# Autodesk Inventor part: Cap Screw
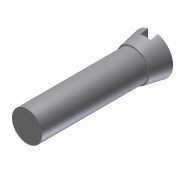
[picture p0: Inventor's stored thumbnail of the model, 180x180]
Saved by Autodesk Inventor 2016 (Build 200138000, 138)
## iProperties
Shininess: 77.0
Length Units: 11269
Angle Units: 11279
Time Units: 11290
Mass Units: 11283
Length Display Precision: 3
Angle Display Precision: 2
Created: 2002-02
Part Number: Cap Screw
Document SubType Name: Modeling
Designer: ***
Density: 1 g/cm^3
Material: Generic
Appearance: Default
Density: 0.0
Volumn: 0.0
Area: 0.0
PropertySet Name: Model Information
Control State: 0
Master: False
Checked Out: False
Author: ***
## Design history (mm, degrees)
sketch "Sketch1"
  geometry: L1 (0, 27.83)-(4, 27.83); L2 (4, 27.83)-(3.25, 23.83); L3 (3.25, 23.83)-(0, 23.83); L4 (0, 23.83)-(0, 27.83)
  constraints: 8 end point, 1 horizontal, 1 parallel, 1 perpendicular, 1 point on line
  dimensions: "d2" = 4 distance from line of L1 L2.end; "d5" = 8 diameter of L1.end L4; "d6" = 6.5 diameter of L3.start L4; "d14" = 4 distance of L3.end L1.start
revolve "Revolution1" sketch "Sketch1" stored, may be unused: angle "d7" = 90 deg
sketch "Sketch2"
  geometry: C1 r 3 at (0, 0)
  constraints: 1 centre point
  dimensions: "d8" = 6 diameter of C1
extrude "Extrusion1" join sketch "Sketch2" distance "d9" = 21; taper "d10" = 0 deg
sketch "Sketch3"
  geometry: L1 (-1, 28.967)-(1, 28.967); L2 (1, 28.967)-(1, 26.33); L3 (1, 26.33)-(-1, 26.33); L4 (-1, 26.33)-(-1, 28.967); L5 (-4, 27.83)-(4, 27.83) reference
  constraints: 8 end point, 2 parallel, 1 horizontal, 1 perpendicular
  dimensions: "d11" = 2 distance of L1.start L1.end; "d15" = 1.5 distance between parallel lines of L5 L3
extrude "Extrusion2" cut sketch "Sketch3" stored distance "d12" = 24; taper "d13" = 0 deg
body "Solid1"
